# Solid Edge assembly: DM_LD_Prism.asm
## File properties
Author: hhakima
Template: Normal.asm
Last saved by: Houman
Revision: 42
Application: Solid Edge
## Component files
Screw_M2.5_12mm_v2.par
Screw_M2.5_12mm_v1.par
Part - Prism.par
LD_Holder_TEC.asm
Part - Back Plate.par
Part - Spring 9002T11 - compressed .par
DM_Assembly.asm
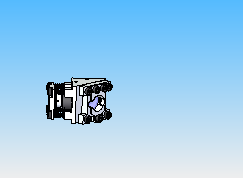
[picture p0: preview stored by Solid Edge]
